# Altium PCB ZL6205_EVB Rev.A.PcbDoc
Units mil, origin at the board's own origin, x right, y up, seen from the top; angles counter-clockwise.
Board outline 866.14 x 866.14 mil, 2 copper layers (Top Layer, Bottom Layer); 17 components, 5 nets, 31 pads, 45 vias.
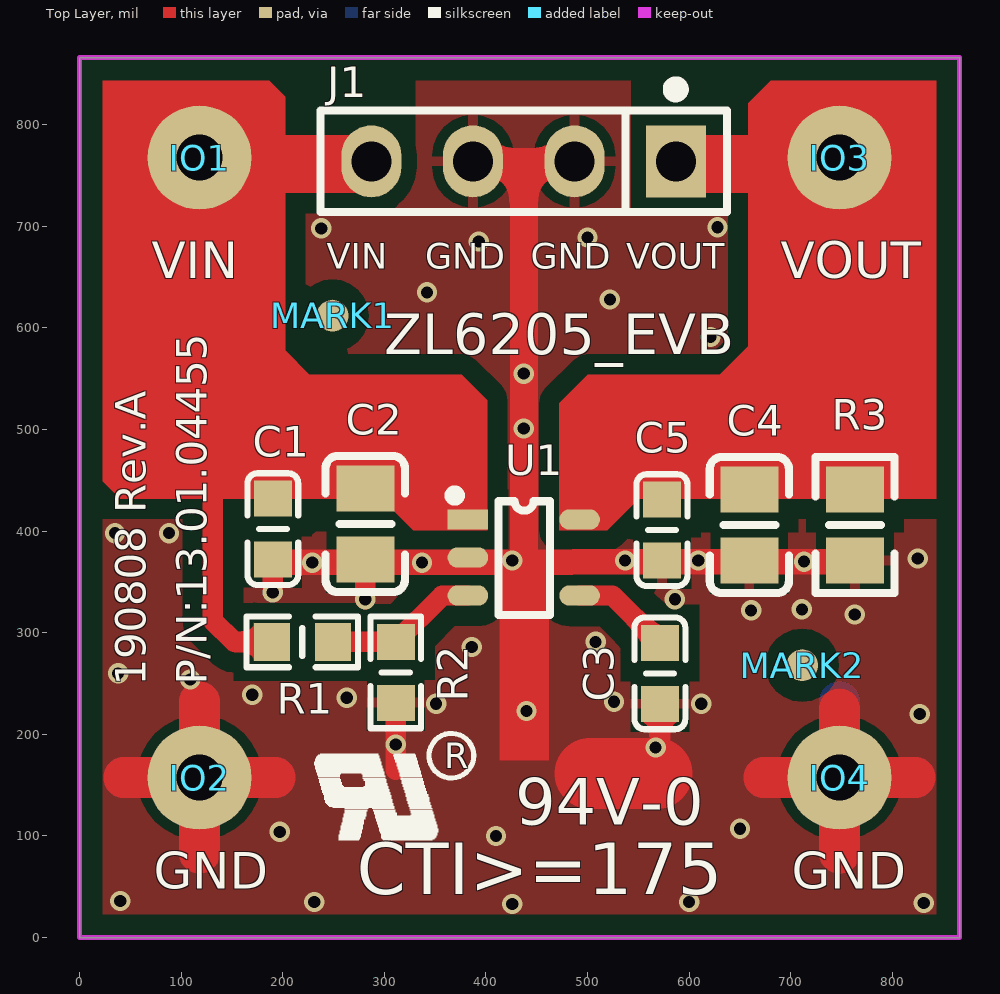
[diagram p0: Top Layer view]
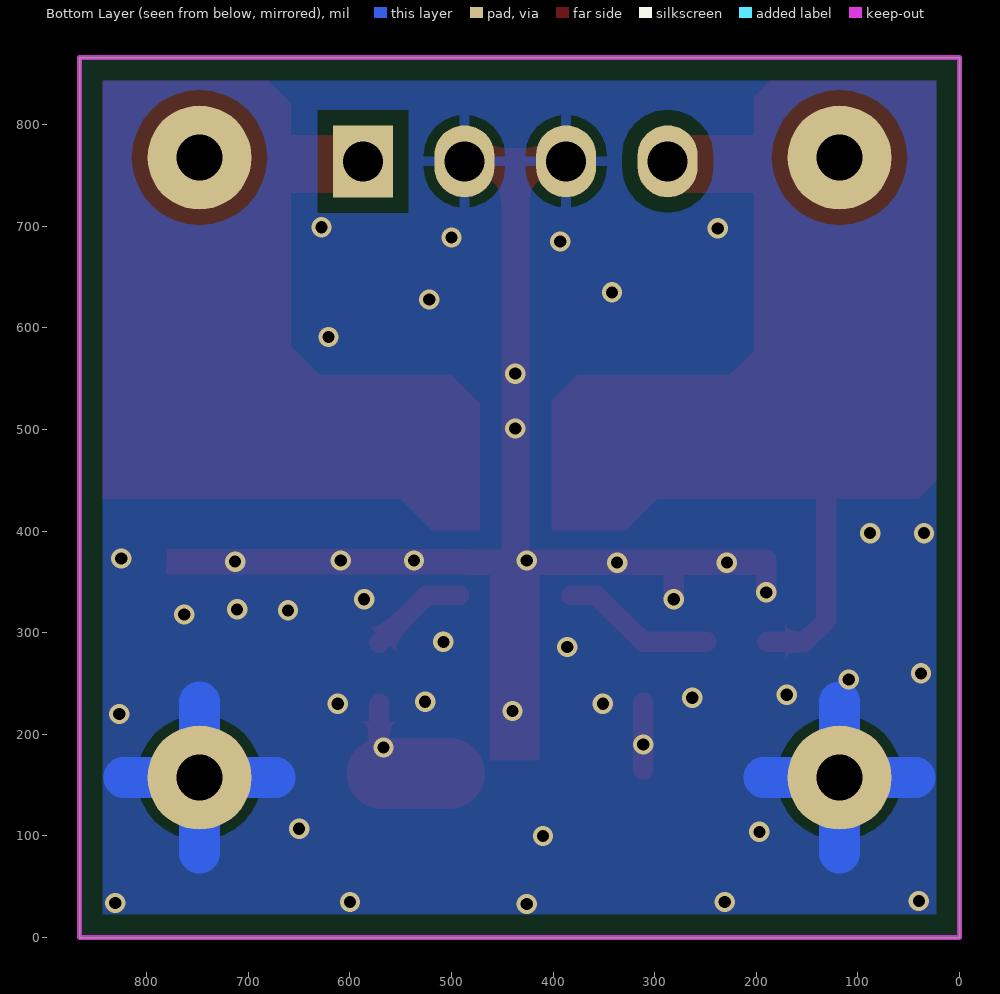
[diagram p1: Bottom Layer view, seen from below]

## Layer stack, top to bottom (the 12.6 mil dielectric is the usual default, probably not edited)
Top Layer: signal copper 1.4
Dielectric: dielectric 12.6, FR-4, Dk 4.8
Bottom Layer: signal copper 1.4

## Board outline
0,0 866.14,0 866.14,866.14 0,866.14

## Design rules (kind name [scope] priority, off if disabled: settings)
Clearance Clearance_INPOLY [inpoly] p1: gap=20
Clearance [All] p2: gap=10
ComponentClearance [All] p1 off: gap=10 collisioncheckmode=3 verticalgap=10 showdistances=FALSE
FabricationTestpoint [(IsPad And (OnTopLayer Or OnBottomLayer))] p1: side=3 testpointundercomponent=TRUE minsize=40 maxsize=100 preferedsize=60 minholesize=0 maxholesize=40 preferedholesize=32 testpointgrid=1 allowsidetop=TRUE allowsidebottom=TRUE usegrid=TRUE gridtolerance=0.01
Height [All] p1 off: minheight=0 maxheight=1000 prefheight=500
MinimumSolderMaskSliver [All] p1 off: minsoldermaskwidth=1
PasteMaskExpansion [All] p1 off: expansion=0
PolygonConnect PolygonConnect_via [isvia] p1: connectstyle=Direct reliefconductorwidth=10 reliefentries=4 polygonreliefangle="90 Angle"
PolygonConnect [All] p2: connectstyle=Relief reliefconductorwidth=10 reliefentries=4 polygonreliefangle="90 Angle"
RoutingVias [All] p1: holewidth=28 width=50 viastyle="Through Hole" minholewidth=15.75 minwidth=31.5 maxholewidth=28 maxwidth=50
SilkToSilkClearance [All] p1 off: silktosilkclearance=10
SilkscreenOverComponentPads [IsPad] p1 off: minsilkscreentomaskgap=0
SolderMaskExpansion [All] p1 off: expansion=4
Width [All] p1: maxlimit=100 minlimit=6 preferedwidth=10
21 further rules are at their usual default settings.

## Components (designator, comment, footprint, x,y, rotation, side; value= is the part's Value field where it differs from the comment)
C1 "0.1uF" 0603C 190.26,402 r270 top
C2 "10uF" 0805C 281.26,407 r270 top
C3 "0.01uF" 0603C 571.26,260 r270 top
C4 "225" 0805C 659.26,406 r270 top
C5 "0.1uF" 0603C 573.26,401 r270 top
IO1 "Φ1.0*16mm,十字引脚" HOLE-1.15X2.6 118.11,767.72 r0 top
IO2 "Φ1.0*16mm,十字引脚" HOLE-1.15X2.6 118.11,157.48 r0 top
IO3 "Φ1.0*16mm,十字引脚" HOLE-1.15X2.6 748.03,767.72 r0 top
IO4 "Φ1.0*16mm,十字引脚" HOLE-1.15X2.6 748.03,157.48 r0 top
J1 "CON4" SIP-4-2.54 437.26,764 r180 top
MARK1 "MARKER" MARKER-C-0.8M 249,612 r90 top
MARK2 "MARKER" MARKER-C-0.8M 711.26,268 r90 top
R1 "51k" 0603R 219.26,291 r180 top
R2 "100k" 0603R 311.26,261 r90 top
R3 "30k,0805" 0805R 763.26,406 r90 top
U1 "ZL6205,SOT-23-5" SOT-23-5 437.26,374 r0 top
UR1 "UR" ZY_UR-3X2 984.26,29 r90 top

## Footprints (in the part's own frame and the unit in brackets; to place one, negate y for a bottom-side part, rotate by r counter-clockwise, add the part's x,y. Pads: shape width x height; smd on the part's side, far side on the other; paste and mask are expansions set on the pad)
0603C [mm]
  rect 0.9x0.95 smd: 1(-0.762,0) 2(0.762,0)
  silkscreen extent -1.4,-0.64 1.4,0.64, body extent -0.79,-0.38 0.81,0.42, height 0.3
0603R [mm]
  rect 0.9x0.95 smd: 1(-0.762,0) 2(0.762,0)
  silkscreen extent -1.4,-0.64 1.4,0.64, body extent -0.8,-0.4 0.8,0.4, height 0.3
0805C [mm]
  rect 1.15x1.45 smd: 1(-0.889,0) 2(0.889,0)
  silkscreen extent -1.7,-0.99 1.7,0.99, body extent -1,-0.63 1,0.63, height 0.78
0805R [mm]
  rect 1.15x1.45 smd: 1(-0.889,0) 2(0.889,0)
  silkscreen extent -1.7,-0.99 1.7,0.99, body extent -1,-0.63 1,0.63, height 0.78
HOLE-1.15X2.6 [mm]
  round 2.6 hole 1.15: 1(0,0)
MARKER-C-0.8M [mm]
  round 0.8 smd paste-1.016 mask+0.4: 0(0,0)
  Top Layer pour cut-out: -0.9,0 -0.831,-0.344 -0.636,-0.636 -0.344,-0.831 0,-0.9 0,-0.9 0.344,-0.831 0.636,-0.636 0.831,-0.344 0.9,0 0.9,0 0.831,0.344 0.636,0.636 0.344,0.831 0,0.9 0,0.9 -0.344,0.831 -0.636,0.636 -0.831,0.344 -0.9,0
SIP-4-2.54 [mm]
  rect 1.5x1.8 hole 1: 1(-3.81,0)
  oval 1.5x1.8 hole 1: 2(-1.27,0) 3(1.27,0) 4(3.81,0)
  silkscreen extent -5.08,-1.92 5.08,1.27, body extent -5.08,-1.27 5.08,1.27, height 7.58
SOT-23-5 [mil]
  rect 40x20 smd: 1(-55,37.4)
  oval 40x20 smd: 2(-55,0) 3(-55,-37.4) 4(55,-37.4) 5(55,37.4)
  silkscreen extent -73,-57 26,66, body extent -55,-57 55,57, height 43
ZY_UR-3X2 [mil]
  silkscreen extent -67,-40 90,65

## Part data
C1 C5: library part 02.01.00015, "C1608X7R1H104KT000N,0603,TDK,0.1uF,X7R,±10%,50V,"
C2: library part 02.01.00174, "GRM21BR61A106KE19L,0805,MURATA,10uF,X5R,±10%,10V,"
C3: library part 02.01.00364, "GCM188R71H103KA15D,103,±10%,50V,X7R,0603,MURATA,"
C4: library part 02.01.00194, "C2012X7R1C225KT000N,0805,TDK,2.2uF,X7R,±10%,16V,"
IO1 IO2 IO3 IO4: library part 24.05.00031, "Φ1.0*16mm,十字引脚,黄铜,"
J1: "Connector"
R1: library part 01.01.00073, "RTT035102DTP,0603,RALEC,51KΩ,±0.5%,1/10W,"
R2: library part 01.01.00031, "RTT03104JTP,0603,RALEC,100KΩ,±5%,1/10W,"
R3: library part 01.01.00305, "RTT05303JTP,0805,RALEC,30KΩ,±5%,1/8W,"
U1: library part ZL6205

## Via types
v1: diameter 20, hole 12, Top Layer to Bottom Layer, tented both sides, 45 vias

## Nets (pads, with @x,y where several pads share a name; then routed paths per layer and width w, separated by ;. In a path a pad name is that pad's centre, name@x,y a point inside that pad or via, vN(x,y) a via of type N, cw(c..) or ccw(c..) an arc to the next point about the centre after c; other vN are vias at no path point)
GND: C1.2 C2.2 C3.2 C4.2 C5.2 IO2.1 IO4.1 J1.2 J1.3 R2.1 R3.1 U1.2 | length 1951.1
  Top Layer w20: v1(190.26,339.7) C1.2 ; v1(281.26,333) C2.2 ; 311.26,165.28 R2.1 ; 502.26,161.28 503.26,162.28 502.26,163.28 ; 571.26,164.28 C3.2
  Top Layer w27.56: J1.3 388.26,763 437.26,763 ; 437.26,376 437.26,763 ; J1.2 486.26,763 437.26,763
  Top Layer w40: 43.7,157.48 IO2.1 ; 118.11,83.07 IO2.1 ; 118.11,231.89 IO2.1 ; 192.52,157.48 IO2.1 ; 673.62,157.48 IO4.1 ; 748.03,83.07 IO4.1 ; 748.03,225 IO4.1 ; 822.44,157.48 IO4.1
  Top Layer w50: IO2.1@117.26,164 IO2.1@119.98,161.28 ; 568.26,161.28 571.26,164.28
  Top Layer w70: 502.26,161.28 568.26,161.28
  Bottom Layer w40: 43.7,157.48 IO2.1 ; 118.11,83.07 IO2.1 ; 118.11,231.89 IO2.1 ; 192.52,157.48 IO2.1 ; 673.62,157.48 IO4.1 ; 748.03,83.07 IO4.1 ; 748.03,231.89 IO4.1 ; 822.44,157.48 IO4.1
  other v1: 426,33 831,34 231,35 600,35 40,36 410,100 197,104 650,107 567,187 311.26,190 827,220 440,223 351,230 612,230 526,232 263,236 170,239 109,254 38,260 386,286 508,291 763,318 661,322 711,323 586,333 229,369 337,369 713,370 426,371 537,371 609,371 825,373 35,398 88,398 437.26,501 437.26,555 621,591 522,628 342,635 393,685 500,689 238,698 628,699
NetC3_1: C3.1 U1.4 | length 98.3
  Top Layer w20: U1.4 524.66,336.6 C3.1
NetR1_1: R1.1 R2.2 U1.3 | length 151.9
  Top Layer w20: R1.1 R2.2 356.86,336.6 U1.3
VCC: C1.1 C2.1 IO1.1 J1.4 R1.2 U1.1 | length 201.8
  Top Layer w20: 136.26,445 131.26,440 131.26,312 152.26,291 R1.2
VOUT: C4.1 C5.1 IO3.1 J1.1 R3.2 U1.5 | length 97.1
  Top Layer w20: C4.1@672.26,454 762.26,454 R3.2@767.26,449
pads on no net: MARK1.0 MARK2.0

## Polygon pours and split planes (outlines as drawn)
GND on Bottom Layer "GND" (solid, remove dead copper, pour order 0): 0,866.14 866.14,866.14 866.14,0 0,0
GND on Top Layer "GND" (solid, remove dead copper, pour order 2): 0,866.14 866.14,866.14 866.14,0 0,0

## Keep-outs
Keep-Out Layer:
  lines w5: 0,0 0,866.14 866.14,866.14 866.14,0 0,0
  lines w10: -3625.74,2154.4 cw(c-3597.44,2182.7) -3625.74,2211 -3013.74,2211 cw(c-3042.54,2183.2) -3014.74,2154.4 -3625.74,2154.4 ; -3625.74,3020.54 cw(c-3597.44,3048.84) -3625.74,3077.14 -3013.74,3077.14 cw(c-3042.54,3049.34) -3014.74,3020.54 -3625.74,3020.54 ; -3625.74,3886.69 cw(c-3597.44,3914.98) -3625.74,3943.28 -3013.74,3943.28 cw(c-3042.54,3915.48) -3014.74,3886.68 -3625.74,3886.69

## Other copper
Top Layer:
  rectangle net VOUT: 587.26,733 696.26,790
  rectangle net VCC: 188.26,733 297.26,790
  rectangle net GND: 413.26,174 462.26,364
  pour cut-out: 542.73,814.43 542.73,864 572,864 572,814.43
  pour cut-out: 330.81,780.22 330.81,847 308,847 308,780.22
  pour cut-out: 101,411.61 -34,411.61 -34,446 101,446
  pour cut-out: 811.8,412.73 811.8,449 861,449 861,412.73
  region net VOUT: 519.26,401 550.26,432 843.2,432 843.2,843.2 680.2,843.2 658.26,821.26 658.26,582 630.26,554 500.26,554 472.26,526 472.26,401
  region net VCC: 401.26,401 401.26,465 391.26,475 208.26,475 208.26,432 297.26,432 328.26,401
  region net GND: 779.83,382.66 780.56,357.67 190.26,356.47 190.26,381.42
  region net VCC: 40,432 22.94,449.06 22.94,843.2 186.8,843.2 202.26,827.74 202.26,741 202.26,578 226.26,554 376.26,554 401.26,529 401.26,465 368.26,432

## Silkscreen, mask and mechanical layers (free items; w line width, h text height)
Top Overlay:
  drawing of 201 lines, arcs and shapes, not listed
  text "VIN" at 243.26,658 h25
  text "GND" at 340.26,658 h25
  text "GND" at 444.26,658 h25
  text "VOUT" at 538.26,658 h25
  text "VIN" at 71,649 h36
  text "VOUT" at 690,649 h36
  text "ZL6205_EVB" at 300,574 h40
  text "P/N:13.01.04455" at 125,249 h30 r90
  text "190808 Rev.A" at 65,248 h30 r90
  text "R" at 359,166.5 h25
  text "94V-0" at 429,111 h46
  text "GND" at 73,48 h36
  text "GND" at 701,48 h36
  text "CTI>=175" at 273,26 h86.61
  text "生产用进板方向，PCB厂忽略" at 2886.57,-174.72 h50
Mechanical 1:
  lines w2: 852.14,-32 866.14,-18 ; 866.14,-89 866.14,-18 ; 880.14,-32 866.14,-18 ; 1718.28,-32 1732.28,-18 ; 1732.28,-89 1732.28,-18 ; 1746.28,-32 1732.28,-18 ; 2584.43,-32 2598.43,-18 ; 2598.43,-89 2598.43,-18 ; 2612.43,-32 2598.43,-18 ; 3496.57,852.14 3482.57,866.14 ; 3496.57,880.14 3482.57,866.14 ; 3496.57,1718.28 3482.57,1732.28 ; 3496.57,1746.28 3482.57,1732.28 ; 3553.57,866.14 3482.57,866.14 ; 3553.57,1732.28 3482.57,1732.28 ; 0,1732.28 866.14,1732.28 ; 0,1732.28 0,2598.43 866.14,2598.43 ; 0,1732.28 866.14,1732.28 ; 0,1732.28 0,866.14 866.14,866.14 ; 866.14,866.14 1732.28,866.14 ; 866.14,866.14 866.14,1732.28 ; 866.14,866.14 866.14,1732.28 ; 866.14,866.14 866.14,0 1732.28,0 ; 866.14,866.14 1732.28,866.14 ; 866.14,1732.28 1732.28,1732.28 ; 866.14,1732.28 866.14,2598.43 ; 866.14,1732.28 866.14,2598.43 ; 866.14,1732.28 1732.28,1732.28 ; 866.14,2598.43 1732.28,2598.43 ; 1732.28,0 2598.43,0 ; 1732.28,0 1732.28,866.14 ; 1732.28,0 1732.28,866.14 ; 1732.28,866.14 2598.43,866.14 ; 1732.28,866.14 1732.28,1732.28 ; 1732.28,866.14 1732.28,1732.28 ; 1732.28,866.14 2598.43,866.14 ; 1732.28,1732.28 2598.43,1732.28 ; 1732.28,1732.28 1732.28,2598.43 ; 1732.28,1732.28 1732.28,2598.43 ; 1732.28,1732.28 2598.43,1732.28 ; 1732.28,2598.43 2598.43,2598.43 ; 2598.43,0 3464.57,0 3464.57,866.14 ; 2598.43,0 2598.43,866.14 ; 2598.43,0 2598.43,866.14 ; 2598.43,866.14 3464.57,866.14 ; 2598.43,866.14 2598.43,1732.28 ; 2598.43,866.14 3464.57,866.14 ; 2598.43,866.14 2598.43,1732.28 ; 2598.43,1732.28 3464.57,1732.28 ; 2598.43,1732.28 2598.43,2598.43 ; 2598.43,1732.28 3464.57,1732.28 ; 2598.43,1732.28 2598.43,2598.43 ; 2598.43,2598.43 3464.57,2598.43 3464.57,1732.28 ; 3464.57,866.14 3464.57,1732.28
  lines w5: 0,0 866.14,0 866.14,866.14 0,866.14 0,0
  text "F" at 402,2015.28 h200
  text "F" at 1268.14,2015.28 h200
  text "F" at 2134.28,2015.28 h200
  text "F" at 3000.43,2015.28 h200
  text "VCUT" at 3557.57,1723.28 h20
  text "F" at 402,1149.14 h200
  text "F" at 1268.14,1149.14 h200
  text "F" at 2134.28,1149.14 h200
  text "F" at 3000.43,1149.14 h200
  text "VCUT" at 3557.57,857.14 h20
  text "F" at 402,283 h200
  text "F" at 1268.14,283 h200
  text "F" at 2134.28,283 h200
  text "F" at 3000.43,283 h200
  text "VCUT" at 857.14,-93 h20 r270
  text "VCUT" at 1723.28,-93 h20 r270
  text "VCUT" at 2589.43,-93 h20 r270
Mechanical 2:
  drawing of 637 lines, arcs and shapes, not listed
  text "PCB加工工艺要求" at 5685,4410 h280
  text "mm x" at 4882,4224 h100
  text "mm" at 5492,4224 h100
  text "88" at 4547,4215 h100
  text "66" at 5157,4215 h100
  text "IPC-600E   IPC-6011/12" at 6650,4214 h100
  text "IPC-Ⅱ" at 7985,4213 h100
  text "IPC-Ⅲ" at 8485,4213 h100
  text "尺寸" at 3993.7,4196.14 h150
  text "验收标准" at 5993.7,4196.14 h150
  text "FR4 TG140" at 4700,4014 h100
  text "FR4 TG170" at 5600,4014 h100
  text "生益有胶材料" at 6500,4014 h100
  text "MEGTRON6" at 7400,4014 h100
  text "其他：" at 8300,4014 h100
  text "板材" at 3992.27,3995.93 h150
  text "单面" at 4700,3814 h100
  text "2" at 5400,3814 h100
  text "4" at 6100,3814 h100
  text "6" at 6800,3814 h100
  text "8" at 7500,3814 h100
  text "10" at 8200,3814 h100
  text "板层" at 3992.27,3795.71 h150
  text "0.4mm" at 4700,3614 h100
  text "0.6mm" at 5250,3614 h100
  text "0.8mm" at 5800,3614 h100
  text "1.0mm" at 6350,3614 h100
  text "1.2mm" at 6900,3614 h100
  text "1.4mm" at 7450,3614 h100
  text "1.6mm" at 8000,3614 h100
  text "1.8mm" at 8550,3614 h100
  text "2.0mm" at 9100,3614 h100
  text "板厚" at 3992.27,3595.5 h150
  text "1/2OZ" at 5930,3414 h100
  text "1OZ" at 6430,3414 h100
  text "2OZ" at 6930,3414 h100
  text "（完成铜厚）" at 4933.3,3401.25 h130
  text "外层" at 4657.05,3395 h150
  text "铜厚" at 3992.13,3393.71 h150
  text "白色" at 5150,3214 h100
  text "其他：" at 5850,3214 h100
  text "丝印颜色" at 3992.13,3194.5 h150
  text "绿色" at 5150,3014 h100
  text "黑色" at 5850,3014 h100
  text "红色" at 6550,3014 h100
  text "蓝色" at 7250,3014 h100
  text "黄色" at 7950,3014 h100
  text "其他：" at 8650,3014 h100
  text "（亮光）" at 4532.5,3001.4 h130
  text "阻焊颜色" at 3992.13,2994.29 h150
  text "沉镍金" at 5150,2814 h100
  text "无铅喷锡" at 5850,2814 h100
  text "电镀镍金" at 6550,2814 h100
  text "电镀软金" at 7250,2814 h100
  text "化学沉锡" at 7950,2814 h100
  text "光板" at 8650,2814 h100
  text "OSP" at 9170,2814 h100
  text "表面处理工艺" at 3992.13,2793.07 h150
  text "无" at 5150,2615 h100
  text "按键镀硬金" at 5570,2615 h100
  text "金手指" at 6290,2615 h100
  text "半孔工艺" at 6980,2615 h100
  text "FPCB补强" at 7670,2615 h100
  text "树脂塞孔" at 8360,2615 h100
  text "电镀填孔" at 9050,2615 h100
  text "特殊工艺" at 3992.13,2593.86 h150
  text "是，但双面开窗除外" at 5150,2414 h100
  text "否" at 6295,2414 h100
  text "按文件" at 6995,2414 h100
  text "是否阻焊塞孔" at 3992.27,2393.21 h150
  text "非拼板" at 5150,2214 h100
  text "拼板" at 5850,2214 h100
  text "分成单板交货" at 6550,2214 h100
  text "交货方式" at 3992.13,2194 h150
  text "Gerber输出：英制、相对零点、抑制前导零、精度2:5" at 3995,2020 h120
  text "Ver 19.01.16" at 8690,1953 h120
  text "NC Drill输出：英制、相对零点、抑制前导零、精度2:4" at 3995,1880 h120
  text "R" at 9041,1750.5 h25
  text "其他说明" at 3990,1705 h150
  text "94V-0" at 9111,1695 h46
  text "标识样式>>>" at 8250,1640 h120
  text "CTI>=175" at 8955,1610 h86.61
  text "1." at 3965,1570 h120
  text "机械1层(*.GM1)为外形铣边；若存在工艺副边，请在副边上增加分流点" at 4090,1570 h120
  text "2." at 3964.89,1440 h120
  text "请用供应商UL认证号，防火等级，CTI等级，生产周期替换板上的UR标识，且保持其位置、方向一致；" at 4090,1440 h120
  text "禁止添加文件中不存在的元素，包括供应商LOGO、无铅、光学基准点等" at 4090,1310 h120
  text "3." at 3965,1180 h120
  text "若焊盘开窗与丝印油冲突，焊盘处需将丝印油掏开，不允许上盘" at 4090,1180 h120
  text "4." at 3965,1060 h120
  text "若存在V-CUT，无特别说明时，须为双面V-CUT，角度30（+-5°），余量按以下表格执行" at 4090,1060 h120
  text "PCB厚度（mm）" at 4521,885 h120
  text "筋厚" at 4186,870 h120
  text "（余量）" at 4136,750 h120
  text "0.6" at 4521,745 h120
  text "0.8" at 4760.62,745 h120
  text "1" at 5056.92,745 h120
  text "1.2" at 5241,745 h120
  text "1.6" at 5481,745 h120
  text "2" at 5766,745 h120
  text "2.5" at 5960.39,745 h120
  text "3" at 6246,745 h120
  text "0.16" at 4491.14,607.5 h120
  text "0.2" at 4761.14,607.5 h120
  text "0.3" at 5001.14,607.5 h120
  text "0.3" at 5237,607.5 h120
  text "0.4" at 5477.52,607.5 h120
  text "0.5" at 5721.29,607.5 h120
  text "0.5" at 5961.14,607.5 h120
  text "最小值" at 4131,605 h120
  text "0.5" at 6200,605 h120
  text "0.32" at 4491.54,470 h120
  text "0.4" at 4760.85,470 h120
  text "0.45" at 4970.99,470 h120
  text "0.5" at 5236.72,470 h120
  text "0.6" at 5480,470 h120
  text "0.7" at 5721.58,470 h120
  text "0.8" at 5961.31,470 h120
  text "0.8" at 6201.12,470 h120
  text "最大值" at 4131,465 h120
  text "5." at 3965,295 h120
  text "PCB做完后，请高温烘烤进行应力释放，再整平（或重物压板烘烤），防止翘曲" at 4090,295 h120
  text "我司生产使用无铅工艺制程" at 4085,154 h120
  text "6." at 3964,150 h120
  text "7." at 3965,10 h120
  text "未尽事项请参照我司《PCB质量补充协议》" at 4085,10 h120

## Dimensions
0,2598.43 to 0,0 on Mechanical 1
3464.57,2598.43 to 0,2598.43 on Mechanical 1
